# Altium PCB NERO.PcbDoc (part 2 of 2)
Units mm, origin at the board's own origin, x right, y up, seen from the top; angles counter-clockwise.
Board outline 53.3 x 68.53 mm, 2 copper layers (Top Layer[1], Bottom Layer[2]), stack 1.636 mm thick; 112 components, 60 nets, 397 pads, 225 vias.
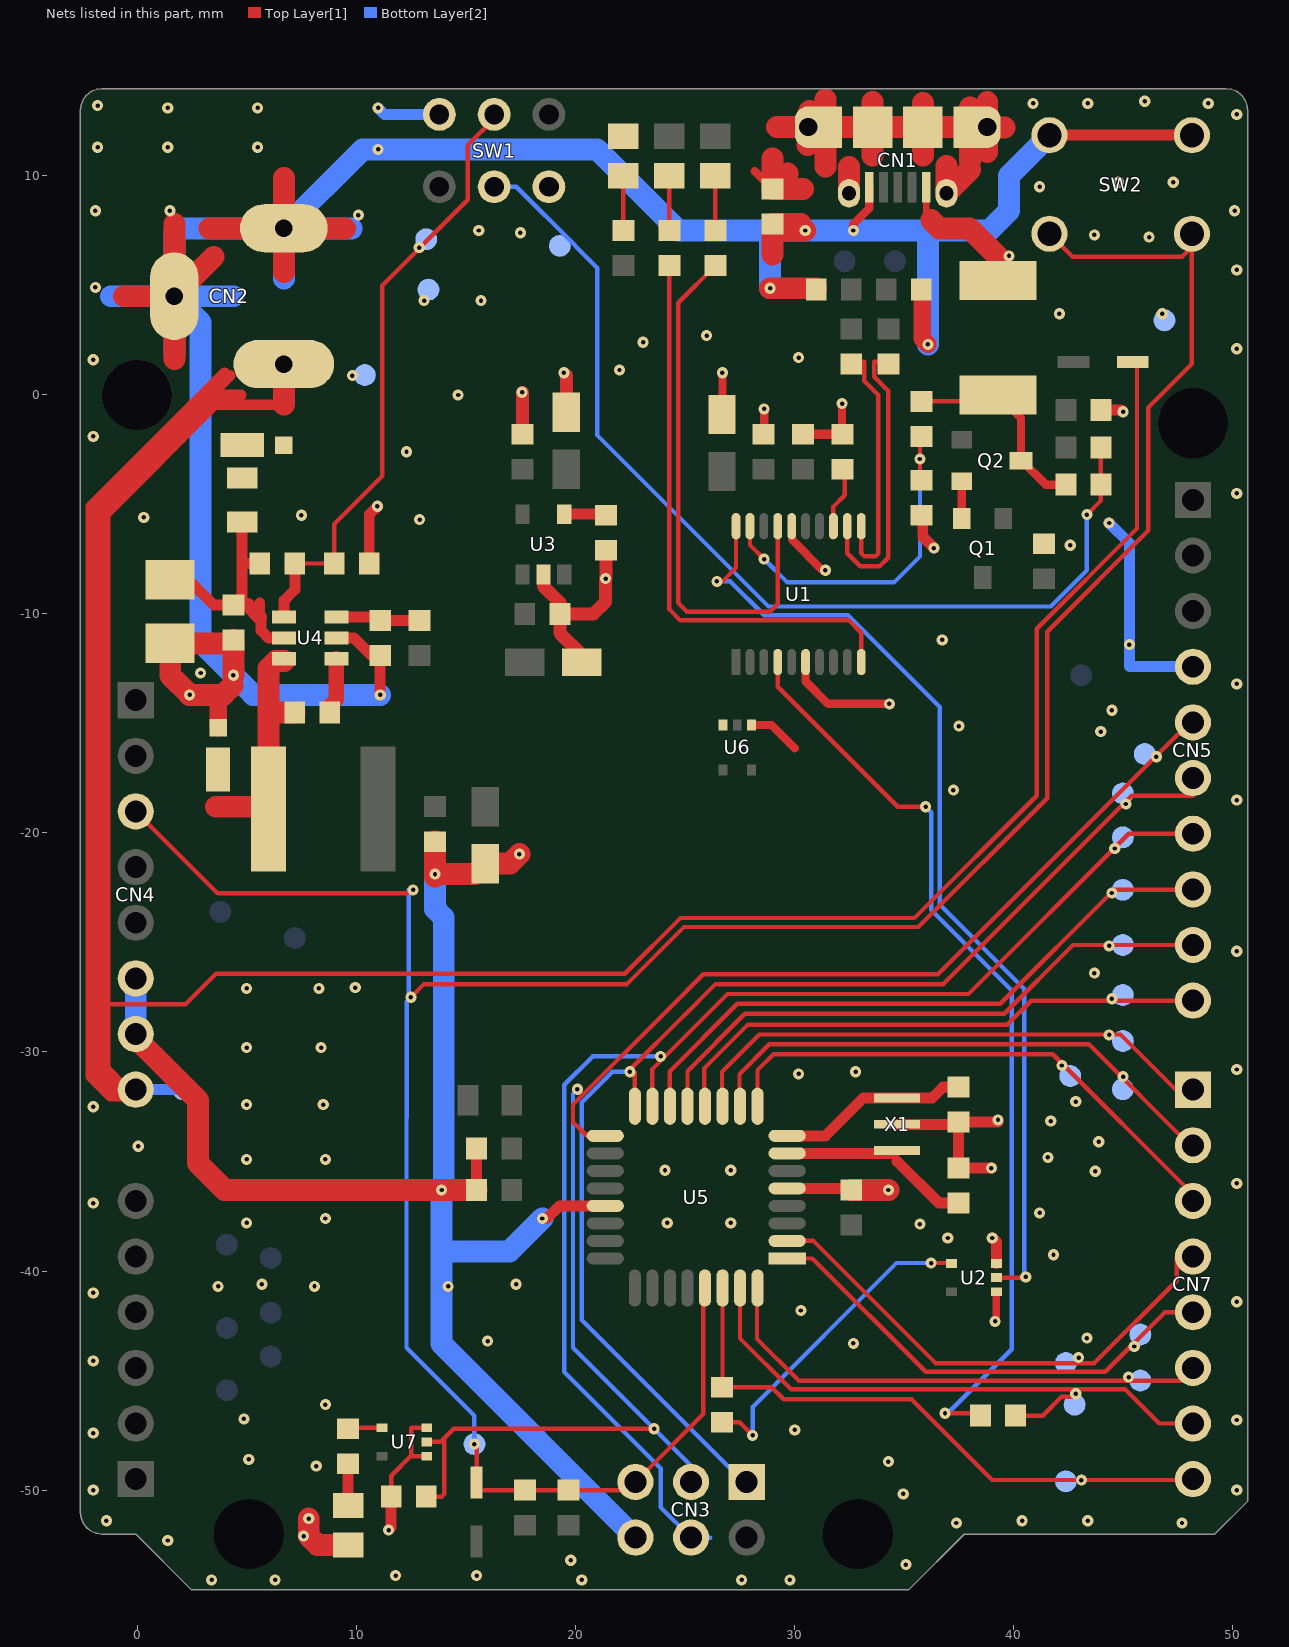
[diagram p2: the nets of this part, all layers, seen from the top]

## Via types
v1: diameter 0.508, hole 0.203, Top Layer[1] to Bottom Layer[2], tented both sides, 225 vias

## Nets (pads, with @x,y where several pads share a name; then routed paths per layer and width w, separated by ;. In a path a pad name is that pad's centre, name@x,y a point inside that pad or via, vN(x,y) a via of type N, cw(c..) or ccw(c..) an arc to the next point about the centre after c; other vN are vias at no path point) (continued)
GND: C1.2 C2.2 C3.2 C4.1 C5.2 C6.2 C7.2 C8.2 C9.2 C10.2 C11.2 C13.2 C14.2 C15.2 C17.1 C18.1 C19.2 C20.2 C21.1 C22.2 C23.2 C24.2 CN1.5 CN2.1 CN2.2 CN3.6 CN4.6 CN4.7 CN5.4 D1.2 GND1.TP GND.TP PWR.1 R11.1 R17.2 R19.2 R21.1 R23.2 SCK.1 SW1.3 SW1.6 SW2.1 SW2.2 U1.6 U1.16 U2.1 U2.3 U3.2 U4.2 U5.5 U5.21 U6.1 U6.3 U7.1 U7.3 X1.2 | length 297.7
  Top Layer[1] w0.2: R23.2@11.6,-50.3 11.6,-49.341 12.521,-48.42 ; U7.1@13.225,-48.45 12.551,-48.45 12.521,-48.42 ; U7.3@13.225,-47.15 12.521,-47.15 12.521,-48.42
  Top Layer[1] w0.35: v1@39.225,-42.244 U2.1@39.225,-40.95
  Top Layer[1] w0.38: C6.2@26.722,-0.521 v1@26.722,0.879 ; U6.1@28.05,-15.075 28.96,-15.075 30.024,-16.139 ; C5.2@28.627,-2.045 v1(28.627,-0.645) ; U1.16@29.883,-6 29.897,-6.015 29.897,-6.614 v1@31.294,-8.011 ; U1.6@30.518,-12.2 30.518,-13.077 31.548,-14.107 v1(34.342,-14.107) ; C4.1@31.7,-1.8 32.183,-1.8 v1(32.183,-0.4) ; v1(32.7,7.5) 32.7,7.8 33.425,8.525 CN1.5@33.425,9.47
  Top Layer[1] w0.45: C7.2@30.4,-1.8 C4.1@32.2,-1.8
  Top Layer[1] w0.5: U4.2@9.1,-11.1 9.9,-11.1 R11.1@10.7,-11.9 ; R19.2@10.6,-7.7 10.6,-5.464 v1(10.974,-5.09) ; v1(11.1,-13.7) R11.1@11.1,-11.9 ; v1@11.6,-51.708 R23.2@11.6,-50.3 ; C21.1@15.5,-36.3 C20.2@15.5,-34.4 ; v1(18.5,-37.6) 18.7,-37.6 19.275,-37.025 U5.21@21.375,-37.025 ; U5.5@29.675,-36.225 C19.2@32.525,-36.225 ; X1.2@34.7,-33.3 C17.1@37.4,-33.3 ; 35.866,-6.487 R21.1@35.866,-5.547 ; 35.946,-6.567 v1(36.374,-6.995) ; v1(39,-35.3) C18.1@37.5,-35.3 C17.1@37.5,-33.2 v1@39.3,-33.2 ; v1(39.041,-38.491) 39.225,-38.675 U2.3@39.225,-39.65 ; SW2.2@41.15,11.85 SW2.2@41.65,11.85 SW2.1@48.15,11.85 ; C15.2@44,-0.7 v1@44.938,-0.7
  Top Layer[1] w0.6: C22.2@17.6,-1.8 v1@17.6,0.095 ; U3.2@18.55,-8.2 18.55,-8.732 19.3,-9.482 ; C23.2@19.6,-0.8 v1@19.6,0.889 ; C8.2@20.3,-12.2 20.3,-11.876 19.3,-10.876 C9.2@19.3,-10 20.837,-10 21.388,-9.449 v1(21.388,-8.392) ; C24.2@21.388,-7.112 C24.2@21.4,-7.1 v1@21.4,-8.38
  Top Layer[1] w0.8: D1.2@3.7,-15.2 3.7,-14 4.4,-13.3 v1(4.4,-12.8) ; C13.2@15.9,-21.446 C13.2@15.9,-21.4 ; C1.2@35.846,4.862 35.846,2.554 v1(36.1,2.3)
  Top Layer[1] w1: -0.6,4.5 CN2.2@1.7,4.5 ; CN4.7@-0.06,-29.18 -0.06,-29.362 2.78,-32.202 2.78,-35.08 4,-36.3 v1(13.9,-36.3) C21.1@15.5,-36.3 ; 1.7,1.623 CN2.2@1.7,4.5 ; 1.7,7.8 CN2.2@1.7,4.5 ; CN2.2@2.1,4.5 CN2.2@1.7,4.5 ; 3.3,7.6 CN2.1@6.7,7.6 ; 3.5,6.3 CN2.2@1.7,4.5 ; C11.2@4.25,-11.35 C10.2@1.5,-11.35 1.516,-11.366 1.516,-12.816 v1(2.4,-13.7) 3.939,-13.7 4.37,-13.27 ; v1(4.4,-12.8) C11.2@4.4,-11.2 ; 6.7,5.6 CN2.1@6.7,7.6 ; 6.7,9.9 CN2.1@6.7,7.6 ; v1(7.838,-51.3) 7.838,-52.1 8.238,-52.5 SCK.1@9.638,-52.5 ; 9.5,7.6 CN2.1@6.7,7.6 ; v1@13.6,-22 C14.2@13.6,-20.4 ; v1(13.601,-21.876) 15.424,-21.876 C13.2@15.9,-21.4 17.016,-21.4 v1(17.451,-20.965) ; v1(28.9,4.862) C2.2@31,4.862 ; 29,6.4 R17.2@29,7.8 ; 30.296,7.8 R17.2@29,7.8 ; v1(30.5,7.5) 29.3,7.5 R17.2@29,7.8 ; C19.2@32.6,-36.3 v1(34.3,-36.3)
  Bottom Layer[2] w0.5: v1(11,13.1) 11.3,12.8 SW1.3@13.8,12.8 ; v1(44.375,-5.852) 45.3,-6.777 45.3,-12.4 CN5.4@48.184,-12.4
  Bottom Layer[2] w1: -1.2,4.5 CN2.2@1.7,4.5 ; CN4.7@-0.06,-29.18 CN4.6@-0.06,-26.64 ; 1.7,1.9 CN2.2@1.7,4.5 ; 4.4,4.5 CN2.2@1.7,4.5 ; 6.7,5.3 CN2.1@6.7,7.6 ; 6.7,9.7 CN2.1@6.7,7.6 ; CN2.1@6.8,7.5 CN2.1@6.7,7.6 ; 9.8,7.6 CN2.1@6.7,7.6 ; v1(11.1,-13.7) 5.3,-13.7 2.9,-11.3 2.9,3.3 CN2.2@1.7,4.5 ; v1(13.601,-21.876) 13.601,-23.465 14,-23.864 14,-36.2 v1(13.9,-36.3) 13.9,-39.1 ; v1(18.5,-37.6) 17,-39.1 13.9,-39.1 ; CN3.6@22.749,-52.167 13.9,-43.318 13.9,-39.1 ; v1(28.9,4.862) 28.9,7.2 ; v1(36.1,2.3) 36.1,7.3 ; 39.8,10 39.8,8.4 38.9,7.5 v1(30.5,7.5) 24.7,7.5 21,11.2 v1(11,11.2) 10.3,11.2 CN2.1@6.7,7.6 ; 39.825,10.025 SW2.2@41.65,11.85 ; CN2.2@1.7,4.5 1.7,7.4 1.9,7.6 CN2.1@6.7,7.6
  other v1: 3.4,-54.1 6.3,-54.1 20.3,-54.1 27.6,-54.1 29.8,-54.1 11.8,-53.9 15.5,-53.9 35.1,-53.4 19.8,-53.2 1.4,-52.3 7.6,-52.1 11.482,-51.826 37.4,-51.5 47.7,-51.5 -1.4,-51.4 40.4,-51.4 43.4,-51.4 34.977,-50.175 -2,-50 50.2,-50 8.18,-48.905 34.3,-48.7 5.1,-48.6 -2,-47.4 30.024,-47.254 50.2,-46.8 4.878,-46.746 8.6,-46.1 -2,-44.1 32.7,-43.3 16,-43.2 43.359,-43.063 39.168,-42.301 30.3,-41.8 50.2,-41.4 -2,-41 3.7,-40.7 8.1,-40.7 14.2,-40.7 5.7,-40.6 17.3,-40.6 41.835,-39.253 37.009,-38.491 35.739,-37.856 5,-37.8 24.2,-37.8 27.1,-37.8 8.6,-37.6 41.2,-37.348 -2,-36.9 50.2,-36 43.74,-35.443 24.1,-35.4 27.1,-35.4 5,-34.9 8.6,-34.9 41.581,-34.808 0.052,-34.3 43.9,-34.1 41.708,-33.157 39.3,-33.1 -2,-32.5 5,-32.4 8.5,-32.4 42.851,-32.268 30.2,-31 32.8,-30.9 50.2,-30.8 5,-29.8 8.4,-29.8 5,-27.1 8.3,-27.1 9.958,-27.061 43.7,-26.4 50.2,-25.4 50.2,-18.5 37.263,-18.044 43.994,-15.377 37.517,-15.123 44.5,-14.4 50.2,-13.2 2.9,-12.7 45.3,-11.4 36.755,-11.186 31.421,-8.011 42.597,-6.868 12.9,-5.7 0.306,-5.598 7.5,-5.5 50.2,-4.5 12.3,-2.6 -2,-1.9 45.01,-0.772 14.657,-0.01 17.578,0.117 19.483,1.006 26.722,1.006 22.023,1.133 -2,1.6 30.2,1.7 50.2,2.1 23.1,2.4 26,2.7 42.1,3.7 46.8,3.7 13.1,4.3 15.7,4.3 -1.9,4.9 50.2,5.7 46.2,7.2 43.7,7.3 17.5,7.4 15.6,7.5 10.1,8.2 -1.9,8.4 1.5,8.4 50.1,8.4 41.2,9.5 44.8,9.7 47.3,9.7 -1.8,11.3 1.4,11.3 5.5,11.3 50.2,12.8 1.4,13.1 5.5,13.1 -1.8,13.2 40.9,13.3 43.4,13.3 48.9,13.3 46,13.4
IO0: CN7.8 R15.2 TP20.TP U5.30 | length 27.6
  Top Layer[1] w0.2: R15.2@26.7,-45.3 28.959,-45.3 29.516,-45.857 35.358,-45.857 39.041,-49.54 CN7.8@48.16,-49.54 ; R15.2@26.725,-44.875 U5.30@26.725,-40.775
  Top Layer[1] w0.38: R15.2@26.7,-45.3 R15.2@26.905,-45.095
  other v1: 43.105,-49.54
IO1: CN7.7 R22.2 TP19.TP U5.31 | length 27.7
  Top Layer[1] w0.2: U5.31@27.525,-40.775 27.525,-43.075 29.85,-45.4 45.1,-45.4 46.66,-46.96 CN7.7@48.2,-46.96 ; R22.2@40.1,-46.6 41.346,-46.6 42.216,-45.73 v1@42.851,-45.73
  other v1: 42.851,-45.603
IO2: CN7.6 TP18.TP U5.32 | length 23.2
  Top Layer[1] w0.2: U5.32@28.3,-40.8 28.3,-43.1 30.2,-45 47.62,-45 CN7.6@48.2,-44.42
  other v1: 45.264,-44.841
IO3: CN7.5 TP17.TP U5.1 | length 21.8
  Top Layer[1] w0.2: U5.1@29.675,-39.425 30.825,-39.425 36,-44.6 44.2,-44.6 46.92,-41.88 CN7.5@48.2,-41.88
  other v1: 45.518,-43.444
IO4: CN7.4 TP16.TP U5.2 | length 22.8
  Top Layer[1] w0.2: U5.2@29.675,-38.625 30.875,-38.625 36.45,-44.2 43.7,-44.2 47.46,-40.44 CN7.4@47.46,-39.34
  other v1: 42.978,-43.952
IO5: CN7.3 TP15.TP U5.9 | length 25.3
  Top Layer[1] w0.2: U5.9@28.325,-32.475 28.325,-30.825 29.05,-30.1 41.8,-30.1 48.2,-36.5 CN7.3@48.2,-37.28
  other v1: 42.216,-30.617
IO6: CN7.2 TP14.TP U5.10 | length 25
  Top Layer[1] w0.2: U5.10@27.525,-32.475 27.5,-32.45 27.5,-31.014 28.864,-29.65 43.45,-29.65 48.2,-34.4 CN7.2@48.2,-34.74
  other v1: 45.01,-31.125
IO7: CN7.1 TP13.TP U5.11 | length 25.2
  Top Layer[1] w0.2: U5.11@26.7,-32.523 26.7,-31.2 26.7,-30.9 28.4,-29.2 44.893,-29.2 CN7.1@48.046,-32.354 ; U5.11@26.725,-32.475 U5.11@26.9,-32.3
  other v1: 44.375,-29.22
IO8: CN5.10 TP8.TP U5.12 | length 25.3
  Top Layer[1] w0.2: U5.12@25.925,-32.475 25.9,-32.45 25.9,-30.736 27.886,-28.75 39.723,-28.75 40.817,-27.656 CN5.10@48.2,-27.656
  other v1: 44.502,-27.569
IO9: CN5.9 TP7.TP U5.13 | length 27
  Top Layer[1] w0.2: U5.13@25.125,-32.475 25.125,-30.875 27.7,-28.3 ; 27.75,-28.25 39.586,-28.25 42.72,-25.116 CN5.9@48.2,-25.116
  other v1: 44.375,-25.156
MISO: CN3.1 CN5.6 TP4.TP U5.16 | length 56
  Top Layer[1] w0.2: v1@22.539,-30.939 22.539,-30.761 24.946,-28.354 24.956,-28.354 26.41,-26.9 36.8,-26.9 45.4,-18.3 CN5.6@48.2,-18.3 ; U5.16@22.725,-32.475 v1@22.725,-30.939
  Bottom Layer[2] w0.2: v1(22.5,-30.9) 21.7,-30.9 20.3,-32.3 20.3,-42.229 27.698,-49.627 CN3.1@27.829,-49.627 CN3.1@27.956,-49.5
  other v1: 45.137,-18.679
MOSI: CN3.4 CN5.7 TP5.TP U5.15 | length 59.7
  Top Layer[1] w0.2: U5.15@23.525,-32.475 23.525,-30.775 26.95,-27.35 37.95,-27.35 45.264,-20.036 CN5.7@48.2,-20.036
  Bottom Layer[2] w0.2: v1(23.9,-30.2) 20.8,-30.2 19.5,-31.5 19.5,-44.604 23.9,-49.004 23.9,-50.778 CN3.4@25.289,-52.167 26.167,-52.167
  other v1: 44.629,-20.711
NetC4_2: C4.2 U1.13 | length 2.7
  Top Layer[1] w0.2: U1.13@31.788,-6 31.788,-5.105 32.31,-4.582 C4.2@32.31,-3.51
NetC10_1: C10.1 C11.1 FB1.1 R9.1 U4.5 | length 12
  Top Layer[1] w0.5: C10.1@1.83,-8.45 2.35,-8.45 3.5,-9.6 C11.1@4.4,-9.6 ; FB1.1@4.8,-5.8 4.8,-7.7 ; 5.05,-9.6 C11.1@4.4,-9.6 ; 5.6,-9.5 5.6,-10.15 5.65,-10.2 5.65,-10.75 6,-11.1 U4.5@6.7,-11.1 ; R9.1@5.6,-7.7 4.8,-7.7 ; C11.1@4.4,-9.6 4.8,-9.2 4.8,-7.7
  Top Layer[1] w0.65: 5.05,-9.6 5.6,-10.15
  Top Layer[1] w1.5: C10.1@1.5,-8.45 C10.1@1.83,-8.45
NetC12_1: C12.1 U4.1 | length 2.6
  Top Layer[1] w0.7: C12.1@8.8,-14.5 8.8,-14.2 9.1,-13.9 U4.1@9.1,-12.05
NetC12_2: C12.2 D1.1 L1.1 U4.6 | length 10.7
  Top Layer[1] w1: 3.6,-18.806 L1.1@5.906,-18.806 ; L1.1@6,-18.9 6,-12.5 6.35,-12.15 U4.6@6.7,-12.15 ; 6.1,-14.5 C12.2@7.2,-14.5
NetC17_2: C17.2 U5.8 X1.1 | length 8.7
  Top Layer[1] w0.5: U5.8@29.675,-33.825 31.425,-33.825 33.15,-32.1 X1.1@34.7,-32.1 36.3,-32.1 36.8,-31.6 C17.2@37.5,-31.6
NetC18_2: C18.2 U5.7 X1.3 | length 8.5
  Top Layer[1] w0.5: U5.7@29.675,-34.625 X1.3@34.575,-34.625 ; 34.7,-35 36.6,-36.9 C18.2@37.5,-36.9
NetC24_1: C24.1 U3.4 | length 1.8
  Top Layer[1] w0.5: U3.4@19.5,-5.45 C24.1@21.35,-5.45
NetCN1_1: CN1.1 F1.1 VBUS.TP | length 6.3
  Top Layer[1] w0.3: 36.025,8.202 CN1.1@36.025,9.47
  Top Layer[1] w1: 36.252,7.975 36.627,7.6 38,7.6 39.3,6.3 F1.1@39.3,5.015
  other v1: 39.803,6.34
NetCN1_6: CN1.6 CN1.7 CN1.8 CN1.9 R17.1 | length 33.6
  Top Layer[1] w0.38: 28.2,10.2 R17.1@29,9.4
  Top Layer[1] w0.5: CN1.6@31.425,12.22 CN1.6@31.445,12.2 ; CN1.7@38.005,12.2 CN1.7@38.025,12.22 CN1.7@38.08,12.22
  Top Layer[1] w1: 29,10.8 R17.1@29,9.4 ; 29.22,12.22 CN1.6@30.64,12.22 CN1.6@31.425,12.22 ; 29.7,10.1 R17.1@29,9.4 ; 30.4,9.4 R17.1@29,9.4 ; CN1.6@30.6,11.395 CN1.6@31.425,12.22 ; CN1.6@30.697,12.948 CN1.6@31.425,12.22 ; 31.425,10.425 CN1.6@31.425,12.22 ; 31.425,13.475 CN1.6@31.425,12.22 ; CN1.8@32.5,9.2 32.5,10.4 ; 33.575,10.925 CN1.9@33.575,12.22 ; 33.575,13.375 CN1.9@33.575,12.22 ; 35.875,10.925 CN1.9@35.875,12.22 ; 35.875,13.325 CN1.9@35.875,12.22 ; 36.95,10.45 CN1.9@36.95,9.2 38.025,10.275 ; CN1.7@37.985,12.22 CN1.9@35.875,12.22 ; 38.025,10.675 CN1.7@38.025,12.22 CN1.7@38.025,13.125 ; 38.81,11.077 CN1.7@38.81,12.22 ; 38.81,13.363 CN1.7@38.81,12.22 ; CN1.7@38.935,12.345 CN1.7@38.81,12.22 ; 39.6,12.2 38.83,12.2 CN1.7@38.81,12.22 ; CN1.6@31.425,12.22 CN1.9@33.575,12.22 ; CN1.9@33.575,12.22 CN1.9@35.875,12.22
NetD3_1: D3.1 FB1.2
NetPWR_2: PWR.2 R7.2 | length 2.5
  Top Layer[1] w0.2: R7.2@22.2,7.5 PWR.2@22.2,10
NetQ1_2: Q1.2 Q2.2 | length 1.7
  Top Layer[1] w0.38: Q1.2@37.65,-5.65 Q2.2@37.65,-3.95
NetR3_1: R3.1 U1.17 | length 24.5
  Top Layer[1] w0.2: R3.1@26.4,5.9 24.7,4.2 24.7,-9.5 25.097,-9.897 28.9,-9.897 29.248,-9.55 U1.17@29.248,-6
NetR3_2: R3.2 TX.1 | length 2.5
  Top Layer[1] w0.2: R3.2@26.4,7.5 TX.1@26.4,10
NetR4_1: R4.1 U1.10 | length 26.2
  Top Layer[1] w0.2: R4.1@24.3,5.9 24.3,-9.8 24.797,-10.297 32.497,-10.297 33.058,-10.858 U1.10@33.058,-12.2
NetR4_2: R4.2 RX.1 | length 2.5
  Top Layer[1] w0.2: R4.2@24.3,7.5 RX.1@24.3,10
NetR6_1: R6.1 U7.4 | length 1.5
  Top Layer[1] w0.2: R6.1@9.688,-47.15 U7.4@11.175,-47.15
NetR6_2: R6.2 SCK.2 | length 1.9
  Top Layer[1] w0.5: SCK.2@9.638,-50.7 R6.2@9.638,-48.8
NetR9_2: R9.2 R19.1 SW1.2 TP21.TP U4.4 | length 27.8
  Top Layer[1] w0.2: R9.2@7.2,-7.7 R19.1@9,-7.7 9,-5.9 10.9,-4 11.2,-3.7 11.2,5 15.1,8.9 15.1,11.4 SW1.2@16.3,12.6
  Top Layer[1] w0.5: U4.4@6.7,-10.15 6.7,-9.4 7.2,-8.9 R9.2@7.2,-7.7
  other v1: 12.879,6.721
NetR10_1: R10.1 R11.2 U4.3 | length 3.7
  Top Layer[1] w0.5: U4.3@9.1,-10.15 R11.2@10.95,-10.15 ; R11.2@11.1,-10.3 R10.1@12.9,-10.3
NetR12_2: R12.2 R13.2 SW1.5 TP22.TP | length 46.4
  Top Layer[1] w0.2: v1(43.359,-5.471) 44,-4.83 R13.2@44,-4.1 R12.2@44,-2.4
  Bottom Layer[2] w0.2: SW1.5@16.3,9.5 17.315,9.5 20.015,6.8 20.015,6.785 21,5.8 21,-1.839 28.823,-9.662 36.861,-9.662 37.771,-9.662 ; 37.411,-9.662 41.708,-9.662 43.359,-8.011 v1(43.359,-5.471)
NetR20_2: R20.2 R21.2 U1.19 | length 16.3
  Top Layer[1] w0.2: U1.19@27.978,-6 27.978,-6.854 v1(28.627,-7.503) ; R21.2@35.739,-3.931 v1(35.739,-2.931) R20.2@35.739,-1.931
  Bottom Layer[2] w0.2: v1(28.627,-7.503) 29.689,-8.565 34.55,-8.565 35.739,-7.376 v1(35.739,-2.931)
RESET: C16.2 CN3.5 CN4.3 D4.2 R14.1 RST.TP SW2.3 SW2.4 U5.29 | length 127.7
  Top Layer[1] w0.2: CN4.3@-0.06,-19.02 3.68,-22.76 12.341,-22.76 v1@12.5,-22.6 ; v1(12.5,-27.5) 13.1,-26.9 22.366,-26.9 24.97,-24.296 35.665,-24.296 41.546,-18.415 41.546,-10.814 46.153,-6.207 46.153,-0.589 48.15,1.408 SW2.3@48.15,6.75 ; D4.2@15.5,-49.65 v1@15.5,-48 ; 15.85,-50 R14.1@17.7,-50 C16.2@19.7,-50 22.376,-50 CN3.5@22.749,-49.627 25.85,-46.526 U5.29@25.85,-40.85 ; R14.1@17.3,-50 R14.1@17.35,-50.05 ; SW2.4@41.65,7.35 42.7,6.3 47.7,6.3 SW2.3@48.15,6.75 ; SW2.3@48.15,7.35 SW2.3@48.15,6.75
  Bottom Layer[2] w0.2: 12.304,-27.696 12.304,-32.996 12.3,-33 12.3,-43.5 15.4,-46.6 v1(15.4,-47.9) ; v1@12.4,-27.4 v1@12.4,-22.6
  other v1: 12.6,-22.6
RXD_3V3: U1.20 U2.2 | length 44.4
  Top Layer[1] w0.2: v1(26.468,-8.519) 26.722,-8.519 27.343,-7.899 U1.20@27.343,-6 ; U2.2@39.225,-40.3 v1@40.534,-40.3
  Bottom Layer[2] w0.2: v1(26.468,-8.519) 27.084,-8.519 28.627,-10.062 32.456,-10.062 36.647,-14.253 36.647,-23.27 40.5,-27.123 v1@40.5,-40.204
  other v1: 40.565,-40.269
RXD_5V: R15.1 U2.4 | length 14.9
  Top Layer[1] w0.2: R15.1@26.7,-46.9 27.5,-46.9 v1(28.1,-47.5) ; v1(36.247,-39.634) U2.4@37.159,-39.634
  Bottom Layer[2] w0.2: v1(28.1,-47.5) 28.1,-46.2 34.666,-39.634 v1(36.247,-39.634)
  Bottom Layer[2] w0.3: v1@28,-47.4 v1(28.1,-47.5)
SCK: CN3.3 CN5.5 R23.1 TP3.TP U5.17 U7.2 | length 72.3
  Top Layer[1] w0.2: U7.2@13.225,-47.8 13.857,-47.8 14.022,-47.635 ; R23.1@13.452,-50.048 R23.1@13.2,-50.3 13.897,-50.3 14.022,-50.175 14.022,-47.635 ; U5.17@21.375,-33.825 20.525,-33.825 19.9,-33.2 19.9,-32.4 24.346,-27.954 25.85,-26.45 36.557,-26.45 CN5.5@48.051,-14.956 ; v1(23.6,-47.2) 14.457,-47.2 14.022,-47.635
  Bottom Layer[2] w0.2: 19.9,-31.9 19.9,-43.5 25.289,-48.889 CN3.3@25.289,-49.627
  other v1: 20.1,-31.7 46.534,-16.52
SS: CN5.8 TP6.TP U5.14 | length 28.9
  Top Layer[1] w0.2: U5.14@24.325,-32.475 24.325,-30.875 27.4,-27.8 39.4,-27.8 44.6,-22.6 CN5.8@48.176,-22.6
  other v1: 44.502,-22.743
TXD_5V: R22.1 U1.4 | length 42.4
  Top Layer[1] w0.2: U1.4@29.248,-12.2 29.248,-13.331 34.723,-18.806 v1(35.993,-18.806) ; v1(36.882,-46.492) 37.428,-46.492 ; 37.495,-46.492 38.392,-46.492 R22.1@38.5,-46.6
  Bottom Layer[2] w0.2: v1(35.993,-18.806) 36.247,-19.06 36.247,-23.505 39.93,-27.188 39.93,-43.571 37.009,-46.492 v1(36.882,-46.492)
USB_N: R2.1 U1.12 | length 13.7
  Top Layer[1] w0.2: U1.12@32.423,-6 32.423,-7.23 32.604,-7.411 32.604,-7.418 33.015,-7.83 33.895,-7.83 34.288,-7.437 34.288,0.178 33.647,0.819 33.647,1.514 34.026,1.514 R2.1@34.14,1.4 ; R2.1@34,1.4 R2.1@34.14,1.4 ; R2.1@34.22,1.32 R2.1@34.14,1.4 ; R2.1@34.3,1.4 R2.1@34.14,1.4
USB_P: R1.2 U1.11 | length 11.8
  Top Layer[1] w0.2: R1.2@32.6,1.4 32.714,1.514 33.193,1.514 33.193,0.631 33.834,-0.01 33.834,-7.249 33.707,-7.376 33.203,-7.376 33.058,-7.23 U1.11@33.058,-6
USBVCC: F1.2 Q2.3 R13.1 R20.1 | length 8.5
  Top Layer[1] w0.2: R20.1@36.2,-0.3 F1.2@39.015,-0.3
  Top Layer[1] w0.38: F1.2@39.3,-0.015 40.35,-1.065 Q2.3@40.35,-3 ; Q2.3@40.38,-3 41.48,-4.1 R13.1@42.2,-4.1
VIN: CN2.3 CN4.8 D2.2 D3.2 DC_IN.TP VIN.TP | length 185.4
  Top Layer[1] w0.2: -1.472,-27.823 2.211,-27.823 3.608,-26.426 22.264,-26.426 24.804,-23.886 35.485,-23.886 41.073,-18.298 41.073,-10.678 45.645,-6.106 45.645,1.305 D2.2@45.45,1.5
  Top Layer[1] w0.5: -1.4,-5.217 -1.4,-5.399 3.545,-0.455 ; CN4.8@-0.583,-31.633 -1.472,-30.744 -1.472,-27.823 -1.472,-4.836 ; CN4.8@-0.354,-32.014 -1.218,-32.014 -2.107,-31.125 -2.107,-5.09 -1.853,-4.836 ; CN4.8@-0.06,-31.72 -1.131,-31.72 -1.853,-30.998 -1.853,-5.217 ; 3.989,1.006 -1.853,-4.836 ; 4.243,0.879 2.91,-0.455 ; 4.751,-0.01 3.989,-0.01 3.545,-0.455 ; 6.7,-0.455 3.545,-0.455 ; -1.853,-5.217 -1.853,-4.836 ; -1.853,-5.217 -1.472,-4.836 ; -1.472,-4.836 2.91,-0.455 ; 2.91,-0.455 3.545,-0.455
  Top Layer[1] w1: 6.7,-0.455 CN2.3@6.7,1.4
  Bottom Layer[2] w0.5: CN4.8@-0.06,-31.72 VIN.TP@2.08,-31.72
  other v1: 9.831,0.879
pads on no net: CN1.4 CN4.1 Designator12.0 Designator12.1 Designator12.2 Designator12.3 Designator12.4 Designator12.9 Designator12.10 SW1.1 SW1.4 U1.2 U1.5 U1.7 U1.8 U1.9 U1.18 U5.3 U5.6 U5.19 U5.22

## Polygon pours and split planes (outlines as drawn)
NetCN1_6 on Top Layer[1] "Top Layer[1]-No Net" (solid, pour order 2): 28,8.855 28,13.269 28,13.955 38.737,13.955 39.273,13.955 40.025,13.955 40.025,9.738 40.025,8.855 36.589,8.855 36.589,10.424 36.482,10.522 33.154,10.522 33.154,8.855
GND on Top Layer[1] "GND" (solid, remove dead copper, pour order 10): -2.295,-51.719 -2.464,-51.508 -2.549,-51.275 -2.591,-51.021 -2.591,12.986 -2.549,13.239 -2.464,13.472 -2.295,13.684 -2.083,13.853 -1.851,13.938 -1.597,13.98 49.693,13.98 49.968,13.938 50.201,13.853 50.413,13.684 50.561,13.472 50.666,13.239 50.709,12.986 50.709,-50.492 49.185,-52.016 37.759,-52.016 35.22,-54.555 2.487,-54.555 -0.052,-52.016 -1.597,-52.016 -1.851,-51.973 -2.083,-51.889
GND on Bottom Layer[2] "GND" (solid, pour order 5): 37.8,-52 35.3,-54.5 31.4,-54.5 29.9,-54.5 19.6,-54.5 15,-54.5 2.6,-54.5 2.5,-54.5 1.9,-53.9 0,-52 -0.1,-52 -1.9,-52 -2,-51.9 -2.6,-51.3 -2.6,-51.2 -2.6,-39.5 -2.6,-35.6 31.6,-35.6 31.7,-35.5 49.9,-35.5 50.7,-35.5 50.7,-50.5 49.3,-51.9 49.2,-52 49.1,-52
GND on Bottom Layer[2] "GND" (solid, pour order 7): -2.6,-39.079 -2.6,-34.6 -2.6,13.2 -2.6,13.3 -1.9,14 -0.2,14 50,14 50.4,13.6 50.7,13.3 50.7,13.1 50.7,-39.059

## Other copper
Top Layer[1]:
  rectangle net +5V: 8.307,-22.362 12.117,-15.631
  region net +5V: 18.467,-9.408 17.959,-8.9 17.959,-7.376 16.689,-7.376 16.689,-13.472 18.594,-13.472 18.594,-11.44 18.467,-11.44
  region net 3.3V: 18.467,-5.979 18.467,-4.582 23.928,-4.582 23.928,-2.55 16.562,-2.55 16.562,-5.979
  region net +5V: 17.324,-19.695 17.324,-15.631 11.736,-15.631 11.736,-19.695
  region net NetCN1_1: 37.5,5.7 35.9,7.3 35.9,8.3 38.9,8.3 41.3,6.1 41.3,2.1 37.5,2.1
  region net VIN: 6.26,-3.038 9.96,-3.038 9.96,4.562 3.86,4.562 3.86,-0.238 6.26,-0.238
  region net NetD3_1: 3.6,-4.25 3.608,-1.407 5.894,-1.407 5.9,-4.25
  region net NetC10_1: 3.5,-4.7 3.5,-6.741 0.179,-6.741 0.179,-9.916 5.8,-9.9 5.8,-4.7
  region net NetC12_2: 7.3,-11.7 7.3,-12.5 7.9,-13.1 7.9,-22.4 3.9,-22.4 2.2,-20.7 2.2,-16 4.8,-16 4.8,-13.9 5.5,-13.2 5.5,-11.7
  region net USBVCC: 39.676,-3.566 39.676,-0.074 39.803,0.053 40.819,0.053 40.819,-3.566
  region net NetQ1_2: 37.136,-6.297 38.279,-6.297 38.279,-3.376 37.136,-3.376
  region net +5V: 41.962,-7.757 41.962,-9.027 37.263,-9.027 37.009,-9.281 37.009,-7.757

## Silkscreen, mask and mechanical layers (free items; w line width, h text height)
Top Overlay:
  lines w0.15: 8.25,-8.462 8.25,-6.938 ; 8.307,-8.462 8.885,-8.462 ; 8.307,-6.938 8.758,-6.938 ; 10.974,-8.45 11.355,-8.45 ; 10.974,-6.98 11.355,-6.98 ; 11.228,-51.064 10.847,-51.064 10.847,-49.54 11.228,-49.54 ; 11.355,-8.392 11.355,-6.995 ; 13.387,-51.064 13.895,-51.064 13.895,-49.54 13.514,-49.54 ; 20.626,-7.249 20.626,-7.884 21.134,-7.884 ; 20.626,-5.344 20.626,-4.709 21.134,-4.709 ; 21.642,-7.884 22.15,-7.884 22.15,-7.249 ; 21.642,-4.709 22.15,-4.709 22.15,-5.344 ; 35.05,-5.725 35.05,-6.233 36.55,-6.233 ; 35.05,-3.693 35.05,-3.185 36.55,-3.185 ; 35.05,-2.169 35.05,-2.677 36.55,-2.677 36.55,-2.169 ; 35.068,-0.094 35.068,0.414 36.55,0.414 36.55,-0.137 ; 36.574,-6.233 36.574,-5.725 ; 36.574,-3.693 36.574,-3.185 ; 38.152,-47.381 37.771,-47.381 37.771,-45.857 38.152,-45.857 ; 40.438,-47.381 40.819,-47.381 40.819,-45.857 40.565,-45.857 40.438,-45.857
  text "OFF" at 11.482,13.071 h0.6
  text "ON" at 19.864,13.071 h0.6
  text "RESET" at 41.8,4.5 h1.3
  text "7 V~ 12 V" at 11.609,1.895 h1.6
  text "SCL" at 44.629,-5.979 h1.2
  text "SDA" at 44.502,-8.011 h1.2
  text "AREF" at 43.791,-10.3 h1.2
  text "GND" at 44.383,-12.9 h1.2
  text "13" at 45.6,-15.5 h1.2
  text "5V" at 1.5,-16.7 h1.2
  text "12" at 45.608,-18 h1.2
  text "RST" at 1.5,-19.7 h1.2
  text "~ 11" at 44.629,-20.584 h1.2
  text "3.3V" at 1.5,-21.9 h1.2
  text "~ 10" at 44.502,-22.997 h1.2
  text "5V" at 1.3,-24.4 h1.2
  text "~ 9" at 45.137,-25.537 h1.2
  text "GND" at 1.4,-27 h1.2
  text "8" at 46.026,-28.077 h1.2
  text "GND" at 1.5,-29.6 h1.2
  text "VIN" at 1.5,-32.1 h1.2
  text "7" at 46.013,-32.3 h1.2
  text "~ 6" at 45.137,-34.681 h1.2
  text "~ 5" at 45.137,-37.094 h1.2
  text "A0" at 1.5,-37.2 h1.2
  text "PWM ~" at 44.121,-39.126 h1 r90
  text "A1" at 1.5,-39.7 h1.2
  text "4" at 45.964,-39.8 h1.2
  text "A2" at 1.5,-42.2 h1.2
  text "~ 3" at 45.137,-42.555 h1.2
  text "A3" at 1.5,-44.7 h1.2
  text "2" at 46,-45 h1.2
  text "A4" at 1.5,-47.2 h1.2
  text "1" at 46.178,-47.3 h1.2
  text "A5" at 1.4,-49.8 h1.2
  text "0" at 46.018,-49.9 h1.2
Bottom Overlay:
  text "www.ftdichip.com" at 33.072,-17.536 h2.2
  text "HW_459  REV1.1" at 30.151,-19.314 h1.5
  text "Made in Europe" at 32.945,-21.346 h2.5
Mechanical 2:
  drawing of 724 lines, arcs and shapes, not listed
Mechanical 4:
  circle w0.064: c50.709,12.986 r0.032
  circle w0.064: c-2.591,12.986 r0.032
  circle w0.064: c2.487,-54.555 r0.032
  circle w0.064: c2.487,13.98 r0.032
Sheet Line:
  drawing of 665 lines, arcs and shapes, not listed
  text "1" at -132.6,53.5 h1.2
  text "2" at -63.025,53.225 h1.2
  text "3" at 6.85,53.175 h1.2
  text "4" at 70.2,52.8 h1.2
  text "Revision History" at -160.525,48.278 h1.2
  text "Changed By" at -70.8,44.025 h1.2
  text "Change description" at -128.825,43.728 h1.2
  text "Date" at -160.55,43.703 h1.2
  text "REV" at -141.175,43.703 h1.2
  text "NG YEE BIN" at -70.5,39.7 h1.2
  text "30/09/2015" at -160.075,39.425 h1.2
  text "Initial Design" at -128.825,39.028 h1.2
  text "1.0" at -138.025,39.003 h1.2
  text "NG YEE BIN" at -70.627,35.382 h1.2
  text "1)Change R1 and R2 From 22OHM 1% to 27OHM 1%" at -128.825,35.345 h1.2
  text "1.1" at -137.87,35.296 h1.2
  text "04/01/2016" at -160.202,35.107 h1.2
  text "2)Add TestPoint For Ease The Production" at -128.698,32.932 h1.2
  text "A" at 106.625,31.6 h1.2
  text "3)Add IRLML6402TRPBF (Q2) in series with Q1" at -128.698,30.646 h1.2
  text "A" at -164.675,28.75 h1.2
  text "And Add 4K7 on R20 and 10K on R21 , VCC of U1" at -128.218,28.692 h1.2
  text "Change to +5V to resolve USB Back Voltage issues" at -129.234,27.041 h1.2
  text "4) Replace U2 with  CAHCT1G125QDCKRQ1" at -132.79,25.009 h1.2
  text "5) Add R22 with 1KOHM in series with UNO Sheild Pin" at -129.996,22.723 h1.2
  text "As Per Original UNO" at -126.567,21.072 h1.2
  text "6) Add  CAHCT1G125QDCKRQ1 on U7" at -131.139,19.294 h1.2
  text "7) Add R23 with 10K" at -129.234,16.881 h1.2
  text "B" at -164.875,-10.075 h1.2
  text "B" at 106.7,-11.35 h1.2
  text "C" at -165.275,-63.25 h1.2
  text "C" at 106.6,-63.8 h1.2
  text "Board finish = Immersion Gold" at -123.352,-88.919 h1.15
  text "BUILD STATISTICS" at -160.748,-91.514 h1.52
  text "Soldermask = Both Sides -BLUE" at -123.352,-91.789 h1.15
  text "Silkscreen = Both Sides / White" at -123.448,-94.525 h1.15
  text "Board: FR4, 1.6mm, 1 oz Cu" at -95.622,-94.686 h1.52
  text "GENERAL" at -160.951,-95.223 h1.02
  text "60" at -151.274,-97.331 h1.02
  text "NETS" at -160.875,-97.382 h0.89
  text "Layer Stack Up Detail for: NERO.PcbDoc" at -121.876,-98.888 h1.1
  text "112" at -151.274,-99.414 h1.02
  text "COMPONENTS" at -160.85,-99.439 h0.89
  text "TITLE:" at -48.185,-99.854 h1.2
  text "Future Technology Devices International Ltd." at 49,-100.325 h1.2
  text "Layer" at -121.876,-101.94 h1.1
  text "PRIMITIVES" at -160.926,-102.919 h1.02
  text "178 Paya Lebar Road," at 49,-103.375 h1.2
  text "Name" at -121.876,-104.14 h1.1
  text "12" at -151.274,-105.053 h1.02
  text "FILLS" at -160.85,-105.078 h0.89
  text "FTDI Nero Board" at -40.475,-105.5 h6
  text "#07-04/05" at 48.95,-106.35 h1.2
  text "14040" at -151.274,-107.11 h1.02
  text "TRACKS" at -160.85,-107.161 h0.89
  text "Top Layer[1]" at -121.876,-108.406 h1.55
  text "D" at 106.7,-108.798 h1.2
  text "D" at -165.175,-109.05 h1.2
  text "141" at -151.274,-109.193 h1.02
  text "STRINGS" at -160.85,-109.244 h0.89
  text "Singapore 409030" at 48.95,-109.275 h1.2
  text "Inspired by Arduino UNO R3" at -40.005,-110.49 h6
  text "68" at -151.274,-111.301 h1.02
  text "ARC'S" at -160.85,-111.352 h0.89
  text "www.ftdichip.com" at 51.35,-112 h1.2
  text "Bottom Layer[2]" at -121.876,-112.881 h1.55
  text "LANDS" at -160.951,-114.374 h1.02
  text "ENGINEER:" at -48.95,-114.7 h1.2
  text "DATE:" at -10.525,-114.7 h1.2
  text "REV:" at 80.55,-114.7 h1.2
  text "PART No.:" at 48.275,-114.775 h1.2
  text "397" at -151.274,-116.508 h1.02
  text "PADS" at -160.85,-116.559 h0.89
  text "*" at 58.375,-117.605 h1.2
  text "NG YEE BIN" at -35,-117.705 h1.2
  text "1.1" at 86.65,-117.875 h1.2
  text "04/01/2016" at -8.815,-118.523 h1.2
  text "225" at -151.274,-118.591 h1.02
  text "VIA'S" at -160.824,-118.616 h0.89
  text "277" at -151.274,-120.591 h1.02
  text "HOLES (Total)" at -160.824,-120.616 h0.89
  text "PCB DESIGNER:" at -48.9,-122.35 h1.2
  text "FILE NAME:" at -10.65,-122.35 h1.2
  text "DWG No.:" at 48.175,-122.35 h1.2
  text "SCALE:" at 80.525,-122.35 h1.2
  text "SCALE:1.00" at 83.525,-125.25 h1.2
  text "PRINT SCALE" at -161.027,-125.426 h1.02
  text "NG YEE BIN" at -35,-125.43 h1.2
  text "HW_459" at 58.375,-125.855 h1.2
  text "NERO" at -8.815,-126.143 h1.2
  text "A4" at 101.05,-127.55 h1.2
  text ".Print_Scale" at -151.325,-127.585 h1.02
  text "4" at 74.39,-131.649 h1.2
  text "1" at -134.975,-131.725 h1.2
  text "2" at -64.125,-131.725 h1.2
  text "3" at 4.575,-131.725 h1.2

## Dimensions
-2.591,-51.021 to 50.709,-50.492 on Sheet Line
49.185,-52.016 to 49.693,13.98 on Sheet Line
35.22,-54.555 to 2.487,-54.555 on Sheet Line
-1.597,13.98 to 2.455,-54.555 on Sheet Line
35.219,-57.014 to 50.7,-57.5 on Sheet Line
2.524,-55.392 to -2.576,-55.392 on Sheet Line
